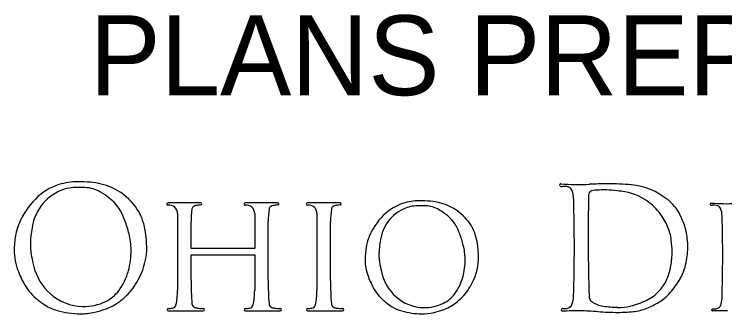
# Model space of a CAD drawing. Extents: x 0 to 34, y 0 to 22.
# Drawn here: x 26.253 to 27.499, y 3.475 to 4.001 of the extents above; entities that cross this region are included whole.
import ezdxf

# ---------------------------------------------------------------- set-up
doc = ezdxf.new("R2010")
doc.units = 0
doc.layers.add('SH_Text', color=7, linetype='Continuous')

msp = doc.modelspace()

# ---------------------------------------------------------------- linework, layer by layer
at = {"layer": 'SH_Text'}
for p, q in [((26.5799, 3.6698), (26.5224, 3.6698)), ((26.7152, 3.6698), (26.6576, 3.6698)), ((26.8245, 3.6698), (26.767, 3.6698)), ((26.5391, 3.6512), (26.5391, 3.516)), ((26.6744, 3.6512), (26.6744, 3.5898)), ((26.7837, 3.6512), (26.7837, 3.516)), ((26.26, 3.6311), (26.26, 3.6311)), ((26.5628, 3.5898), (26.5628, 3.6372)), ((26.698, 3.5337), (26.698, 3.6372)), ((26.8073, 3.5337), (26.8073, 3.6372)), ((26.8744, 3.6086), (26.8744, 3.6086)), ((26.6744, 3.5898), (26.5628, 3.5898)), ((26.5628, 3.5337), (26.5628, 3.5787)), ((26.5628, 3.5787), (26.6744, 3.5787)), ((26.6744, 3.5787), (26.6744, 3.516)), ((26.5228, 3.4804), (26.5841, 3.4804)), ((26.658, 3.4804), (26.7193, 3.4804)), ((26.7673, 3.4804), (26.8286, 3.4804))]:
    msp.add_line(p, q, dxfattribs=at)
for centre, radius, start, end in [((26.3618, 3.6053), 0.1014, 107.613, 135.2994), ((26.3635, 3.5999), 0.107, 90.0889, 107.613), ((26.3638, 3.41), 0.2969, 85.6243, 90.0889), ((26.3781, 3.5963), 0.1101, 65.7405, 85.6243), ((27.2114, 3.7011), 0.0022, 85.6429, 267.986), ((27.2435, 4.1219), 0.4198, 265.6429, 272.4818), ((27.3045, 2.7151), 0.9883, 90.6415, 92.4818), ((27.2976, 3.3252), 0.3781, 84.3199, 90.6415), ((26.3667, 3.6147), 0.0835, 116.7026, 147.5385), ((26.3602, 3.6278), 0.0689, 93.5922, 116.7026), ((26.3685, 3.4957), 0.2013, 87.6816, 93.5922), ((26.3742, 3.6373), 0.0595, 59.809, 87.6816), ((26.3779, 3.596), 0.1105, 40.354, 65.7405), ((27.215, 3.8015), 0.1027, 267.986, 269.6056), ((27.2132, 3.5437), 0.1551, 87.8585, 89.6056), ((27.2182, 3.6778), 0.0209, 70.7604, 87.8585), ((27.2219, 3.6883), 0.0098, 19.7623, 70.7604), ((27.1866, 3.6757), 0.0473, 1.7776, 19.7623), ((27.2687, 3.6831), 0.00866, 94.329, 166.7992), ((27.2936, 3.353), 0.3397, 91.9186, 94.329), ((27.2874, 3.54), 0.1526, 84.8974, 91.9186), ((27.2586, 3.2176), 0.4763, 82.8496, 84.8974), ((27.3053, 3.5896), 0.1014, 55.5454, 82.8496), ((27.3231, 3.581), 0.1211, 51.3332, 84.3199), ((26.3353, 3.5704), 0.1369, 52.0865, 59.809), ((26.3719, 3.6175), 0.0773, 29.7562, 52.0865), ((24.3898, 3.5943), 2.8453, 358.2224, 1.6678), ((30.9231, 3.6105), 3.6638, 178.862, 181.6334), ((27.2687, 3.6831), 0.00866, 166.7992, 178.862), ((26.386, 3.5814), 0.1354, 135.2994, 157.2066), ((26.3965, 3.6118), 0.086, 14.436, 40.354), ((26.5224, 3.6678), 0.00203, 90, 277.32), ((26.5245, 3.6512), 0.0146, 0, 97.32), ((26.5778, 3.6417), 0.0242, 95.8947, 114.8736), ((26.5932, 3.4928), 0.174, 94.3316, 95.8947), ((26.5799, 3.668), 0.00179, 274.3316, 90), ((26.6576, 3.6678), 0.00203, 90, 277.32), ((26.6598, 3.6512), 0.0146, 0, 97.32), ((26.713, 3.6417), 0.0242, 95.8947, 114.8736), ((26.7284, 3.4928), 0.174, 94.3316, 95.8947), ((26.7152, 3.668), 0.00179, 274.3316, 90), ((26.767, 3.6678), 0.00203, 90, 277.32), ((26.7691, 3.6512), 0.0146, 0, 97.32), ((26.8224, 3.6417), 0.0242, 95.8947, 114.8736), ((26.8377, 3.4928), 0.174, 94.3316, 95.8947), ((26.8245, 3.668), 0.00179, 274.3316, 90), ((26.9615, 3.5865), 0.0867, 107.613, 135.2994), ((26.9601, 3.6058), 0.0589, 93.5922, 116.7026), ((26.9629, 3.5819), 0.0916, 90.0889, 107.613), ((26.9672, 3.4927), 0.1722, 87.6816, 93.5922), ((26.9632, 3.4195), 0.254, 85.6243, 90.0889), ((26.9721, 3.6139), 0.0509, 59.809, 87.6816), ((26.9754, 3.5789), 0.0942, 65.7405, 85.6243), ((26.9753, 3.5786), 0.0945, 40.354, 65.7405), ((27.3075, 3.5928), 0.0974, 36.7351, 55.5454), ((27.3475, 3.6115), 0.0821, 27.6817, 51.3332), ((27.4752, 3.6676), 0.00186, 85.6429, 267.986), ((27.4782, 3.7527), 0.087, 267.986, 269.6056), ((27.5024, 4.0242), 0.3557, 265.6429, 272.4818), ((27.4767, 3.5342), 0.1315, 87.8585, 89.6056), ((27.481, 3.6479), 0.0177, 70.7604, 87.8585), ((27.4841, 3.6568), 0.00831, 19.7623, 70.7604), ((26.3667, 3.6147), 0.0835, 147.5385, 165.5071), ((26.3421, 3.6004), 0.1115, 20.2973, 29.7562), ((26.7217, 3.6372), 0.1589, 172.0456, 180), ((26.5701, 3.6584), 0.00585, 114.8736, 172.0456), ((26.857, 3.6372), 0.1589, 172.0456, 180), ((26.7053, 3.6584), 0.00585, 114.8736, 172.0456), ((26.9663, 3.6372), 0.1589, 172.0456, 180), ((26.8147, 3.6584), 0.00585, 114.8736, 172.0456), ((26.9657, 3.5946), 0.0714, 116.7026, 147.5385), ((26.9388, 3.5567), 0.1171, 52.0865, 59.809), ((27.4542, 3.646), 0.0401, 1.7776, 19.7623), ((26.9822, 3.5661), 0.1159, 135.2994, 157.2066), ((26.9701, 3.5969), 0.0661, 29.7562, 52.0865), ((26.9912, 3.5921), 0.0736, 14.436, 40.354), ((27.2948, 3.5833), 0.1133, 23.505, 36.7351), ((27.3099, 3.5918), 0.1245, 17.0568, 27.6817), ((25.0841, 3.5771), 2.4112, 358.2224, 1.6678), ((26.3345, 3.6017), 0.0801, 158.442, 167.8164), ((26.386, 3.5814), 0.1354, 157.2066, 158.442), ((26.4472, 3.5956), 0.1662, 167.8795, 178.2857), ((26.4084, 3.6039), 0.1265, 165.5071, 167.8795), ((26.2446, 3.5644), 0.2156, 13.7527, 20.2973), ((26.3186, 3.5918), 0.1664, 0.6253, 14.436), ((26.9657, 3.5946), 0.0714, 147.5385, 165.5071), ((26.9447, 3.5824), 0.0954, 20.2973, 29.7562), ((27.3205, 3.5945), 0.0852, 6.7275, 23.505), ((27.318, 3.5943), 0.116, 0.2266, 17.0568), ((26.417, 3.5839), 0.1645, 167.8164, 176.8679), ((26.3291, 3.585), 0.1286, 1.1426, 13.7527), ((26.8612, 3.5515), 0.1844, 13.7527, 20.2973), ((26.9381, 3.5835), 0.0685, 158.442, 167.8164), ((26.9822, 3.5661), 0.1159, 157.2066, 158.442), ((27.0346, 3.5782), 0.1422, 167.8795, 178.2857), ((27.0014, 3.5854), 0.1082, 165.5071, 167.8795), ((26.9246, 3.5749), 0.1424, 0.6253, 14.436), ((27.2166, 3.5823), 0.1899, 0.6041, 6.7275), ((26.3593, 3.5871), 0.1067, 176.8679, 187.4835), ((26.3955, 3.5972), 0.1145, 178.2857, 190.5998), ((26.3669, 3.5923), 0.1182, 333.1433, 0.6253), ((27.0087, 3.5682), 0.1407, 167.8164, 176.8679), ((26.9335, 3.5692), 0.11, 1.1426, 13.7527), ((27.2887, 3.5941), 0.1454, 348.6268, 0.2266), ((26.3297, 3.5851), 0.1279, 344.2873, 1.1426), ((26.9903, 3.5796), 0.0979, 178.2857, 190.5998), ((27.2715, 3.5829), 0.135, 349.9228, 0.6041), ((26.345, 3.5852), 0.0923, 187.4835, 199.5864), ((26.5529, 3.6266), 0.2746, 190.5998, 194.5022), ((26.9594, 3.5709), 0.0913, 176.8679, 187.4835), ((26.934, 3.5692), 0.1095, 344.2873, 1.1426), ((26.9659, 3.5754), 0.1011, 333.1433, 0.6253), ((27.3331, 3.5852), 0.1001, 328.8631, 348.6268), ((26.4239, 3.6132), 0.176, 199.5864, 208.6065), ((26.3796, 3.5818), 0.0956, 194.5022, 227.8932), ((26.9471, 3.5693), 0.0789, 187.4835, 199.5864), ((27.125, 3.6048), 0.2349, 190.5998, 194.5022), ((27.2955, 3.5786), 0.1106, 337.2804, 349.9228), ((26.351, 3.5791), 0.1059, 323.2967, 344.2873), ((27.0146, 3.5933), 0.1505, 199.5864, 208.6065), ((26.9767, 3.5664), 0.0818, 194.5022, 227.8932), ((26.353, 3.5746), 0.0952, 208.6065, 229.3453), ((26.3599, 3.5958), 0.126, 316.7511, 333.1433), ((27.0877, 3.5337), 0.5249, 180, 184.4616), ((27.2229, 3.5337), 0.5249, 180, 184.4616), ((27.3322, 3.5337), 0.5249, 180, 184.4616), ((26.9522, 3.5641), 0.0906, 323.2967, 344.2873), ((26.9599, 3.5784), 0.1078, 316.7511, 333.1433), ((27.336, 3.5616), 0.0666, 316.2141, 337.2804), ((27.2981, 3.6064), 0.141, 316.6969, 328.8631), ((26.3859, 3.553), 0.0623, 296.3448, 323.2967), ((26.4216, 3.516), 0.1175, 347.6428, 360), ((26.5569, 3.516), 0.1175, 347.6428, 360), ((26.6662, 3.516), 0.1175, 347.6428, 360), ((26.9539, 3.5602), 0.0815, 208.6065, 229.3453), ((27.325, 3.5722), 0.0819, 297.1175, 316.2141), ((26.3785, 3.6043), 0.1343, 229.3453, 237.7571), ((26.3746, 3.5763), 0.0882, 227.8932, 268.7516), ((26.377, 3.5797), 0.1025, 306.2827, 316.7511), ((26.9725, 3.5617), 0.0755, 227.8932, 268.7516), ((26.9821, 3.5418), 0.0533, 296.3448, 323.2967), ((26.9745, 3.5647), 0.0877, 306.2827, 316.7511), ((27.1864, 3.5075), 0.0473, 340.2377, 358.2224), ((27.2726, 3.5064), 0.0118, 181.6334, 198.7573), ((27.2726, 3.5064), 0.0118, 198.7573, 233.0825), ((27.3409, 3.566), 0.0821, 301.0688, 316.6969), ((27.454, 3.5035), 0.0401, 340.2377, 358.2224), ((26.3495, 3.5584), 0.0801, 237.7571, 254.2366), ((26.3746, 3.5758), 0.0877, 268.7516, 296.3448), ((26.3793, 3.5766), 0.0986, 289.5494, 306.2827), ((26.5293, 3.4924), 0.00731, 275.8469, 347.6428), ((26.5714, 3.4934), 0.00704, 184.4616, 238.9441), ((26.6645, 3.4924), 0.00731, 275.8469, 347.6428), ((26.7066, 3.4934), 0.00704, 184.4616, 238.9441), ((26.7738, 3.4924), 0.00731, 275.8469, 347.6428), ((26.8159, 3.4934), 0.00704, 184.4616, 238.9441), ((26.9757, 3.5856), 0.1149, 229.3453, 237.7571), ((26.9725, 3.5613), 0.075, 268.7516, 296.3448), ((26.9765, 3.562), 0.0844, 289.5494, 306.2827), ((27.2217, 3.4949), 0.0098, 289.2396, 340.2377), ((27.2916, 3.5317), 0.0435, 233.0825, 262.024), ((27.3084, 3.6047), 0.1184, 282.4077, 297.1175), ((27.3068, 3.6226), 0.1481, 292.086, 301.0688), ((27.4839, 3.4928), 0.00831, 289.2396, 340.2377), ((26.3704, 3.6323), 0.1569, 254.2366, 269.1033), ((26.3696, 3.5812), 0.1058, 269.1033, 283.3048), ((26.3534, 3.6495), 0.176, 283.3048, 289.5494), ((26.5228, 3.4825), 0.00215, 91.3892, 270), ((26.5204, 3.5787), 0.094, 271.3892, 275.8469), ((26.5751, 3.4995), 0.0142, 238.9441, 264.1674), ((26.591, 3.656), 0.1715, 264.1674, 267.7015), ((26.5841, 3.4825), 0.00214, 270, 87.7015), ((26.658, 3.4825), 0.00215, 91.3892, 270), ((26.6557, 3.5787), 0.094, 271.3892, 275.8469), ((26.7103, 3.4995), 0.0142, 238.9441, 264.1674), ((26.7263, 3.656), 0.1715, 264.1674, 267.7015), ((26.7193, 3.4825), 0.00214, 270, 87.7015), ((26.7673, 3.4825), 0.00215, 91.3892, 270), ((26.765, 3.5787), 0.094, 271.3892, 275.8469), ((26.8196, 3.4995), 0.0142, 238.9441, 264.1674), ((26.8356, 3.656), 0.1715, 264.1674, 267.7015), ((26.8286, 3.4825), 0.00214, 270, 87.7015), ((26.951, 3.5464), 0.0686, 237.7571, 254.2366), ((26.9689, 3.6096), 0.1343, 254.2366, 269.1033), ((26.9682, 3.5659), 0.0905, 269.1033, 283.3048), ((26.9543, 3.6243), 0.1505, 283.3048, 289.5494), ((27.2141, 3.4823), 0.00208, 90.3944, 271.2938), ((27.213, 3.6395), 0.1551, 270.3944, 272.1415), ((27.2387, 2.3916), 1.0888, 89.661, 91.2938), ((27.218, 3.5053), 0.0209, 272.1415, 289.2396), ((27.2426, 3.0367), 0.4437, 85.604, 89.661), ((27.3104, 3.9194), 0.4415, 265.604, 270.141), ((27.3139, 3.6906), 0.2039, 262.024, 269.0831), ((27.3122, 3.5872), 0.1006, 269.0831, 282.4077), ((27.3108, 3.7475), 0.2696, 270.141, 275.8096), ((27.3291, 3.5675), 0.0887, 275.8096, 292.086), ((27.4775, 3.4821), 0.00177, 90.3944, 271.2943), ((27.4766, 3.6154), 0.1315, 270.3944, 272.1415), ((27.4984, 2.5579), 0.9227, 89.661, 91.2938), ((27.4808, 3.5017), 0.0177, 272.1415, 289.2396)]:
    msp.add_arc(centre, radius, start, end, dxfattribs=at)

# ---------------------------------------------------------------- texts
msp.add_text('PLANS PREPARED BY:', height=0.14, dxfattribs=at).set_placement((26.3847, 3.8587))

doc.saveas('drawing.dxf')
